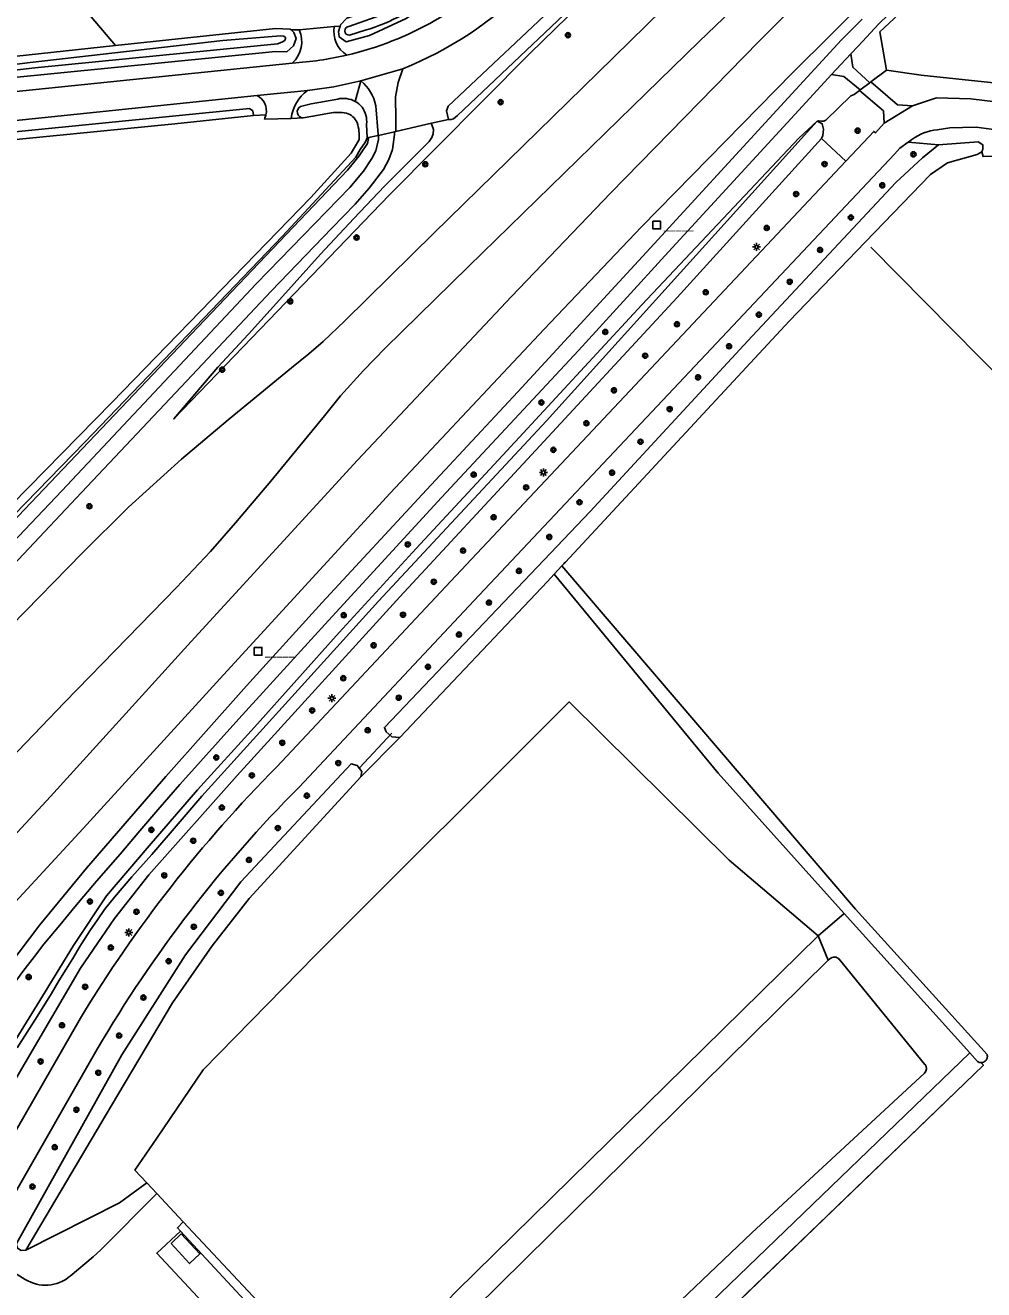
# Model space of a CAD drawing. Extents: x 141000 to 143000, y 400580 to 403500.
# Drawn here: x 141131.1 to 141280.9, y 401460.8 to 401658.2 of the extents above; entities that cross this region are included whole.
import ezdxf

# ---------------------------------------------------------------- set-up
doc = ezdxf.new("R2010")
doc.units = 0
for name, color, linetype in [('gg-afsc-muur', 7, 'Continuous'), ('gg-bbg-luifel en loopbrug', 7, 'Continuous'), ('gg-knt-bronhoudergrens', 7, 'Continuous'), ('gg-knt-onverhard', 7, 'Continuous'), ('gg-knt-verharding', 7, 'Continuous'), ('gg-knt-verharding nz', 7, 'Continuous'), ('gg-kntw-bovenkant insteek waterloop', 7, 'Continuous'), ('gg-kntw-waterlijn', 7, 'Continuous'), ('gg-kwrk-duiker nz buis', 7, 'Continuous'), ('gt-grn-groengrens', 7, 'Continuous'), ('gt-grn-groengrens NZ', 7, 'Continuous'), ('gt-symb-boom', 7, 'Continuous'), ('gt-symb-hm paal', 7, 'Continuous'), ('gt-symb-lichtmast', 7, 'Continuous'), ('gx-grn-maaiveld', 7, 'Continuous')]:
    doc.layers.add(name, color=color, linetype=linetype)

# ---------------------------------------------------------------- blocks, each defined once
blk = doc.blocks.new('gt0-BOOM')
at = {"layer": 'gt-symb-boom'}
for radius in [0.4, 0.2]:
    blk.add_circle((0, 0), radius, dxfattribs=at)
blk = doc.blocks.new('gt0-LMAST')
at = {"layer": 'gt-symb-lichtmast'}
for p, q in [((-0.18, 0.17), (-0.45, 0.44)), ((-0.01, 0.25), (-0.01, 0.62)), ((0.17, 0.17), (0.44, 0.44)), ((-0.26, 0), (-0.63, 0)), ((-0.18, -0.18), (-0.45, -0.45)), ((-0.01, -0.25), (-0.01, -0.63)), ((0.44, -0.45), (0.17, -0.18)), ((0.24, 0), (0.62, 0))]:
    blk.add_line(p, q, dxfattribs=at)
blk.add_circle((-0.01, 0), 0.25, dxfattribs=at)
blk = doc.blocks.new('gt0-HMpaal')
at = {"layer": 'gt-symb-hm paal'}
blk.add_lwpolyline([(-0.6, 0.6), (0.6, 0.6), (0.6, -0.6), (-0.6, -0.6)], close=True, dxfattribs=at)

msp = doc.modelspace()

# ---------------------------------------------------------------- linework, layer by layer
at = {"layer": 'gg-afsc-muur'}
msp.add_line((141190.81, 401409.23), (141280.81, 401495.86), dxfattribs=at)
for points in [[(141307.58, 401634.89), (141295.31, 401636.59), (141285.65, 401637.86), (141280.75, 401637.75)], [(141263.19, 401623.61), (141314.31, 401571.92), (141364.95, 401627.66)], [(141184.12, 401449.64), (141179.93, 401445.63), (141155.78, 401471.4), (141151.62, 401475.84), (141150.06, 401477.51), (141148.21, 401479.48), (141151.64, 401484.46)]]:
    msp.add_lwpolyline(points, dxfattribs=at)
at = {"layer": 'gg-bbg-luifel en loopbrug'}
msp.add_lwpolyline([(141153.86, 401468), (141156.77, 401464.88), (141158.38, 401466.39), (141155.47, 401469.51), (141153.86, 401468)], dxfattribs=at)
at = {"layer": 'gg-knt-bronhoudergrens'}
for p, q in [((141173.89, 401657.55), (141172.61, 401657.51)), ((141180.27, 401658.13), (141179.37, 401658.04)), ((141166.74, 401644.18), (141168.69, 401644.28)), ((141174.53, 401643.79), (141172.64, 401643.69)), ((141256.57, 401512.25), (141256.8, 401512.48)), ((141271.67, 401495.99), (141258.28, 401512.4))]:
    msp.add_line(p, q, dxfattribs=at)
for points in [[(141176.05, 401415.05), (141172.39, 401419), (141180.43, 401426.48), (141176.54, 401431.16), (141193.37, 401447.27), (141193.37, 401449.96), (141256.57, 401512.25)], [(141186.39, 401414.96), (141190.57, 401418.94), (141206.75, 401434.41), (141220.25, 401446.49), (141244.63, 401469.68), (141271.58, 401494.63)]]:
    msp.add_lwpolyline(points, dxfattribs=at)
for centre, start, end in [((141257.51, 401511.76), 39.2641, 134.5353), ((141270.9, 401495.36), 312.8405, 39.1195)]:
    msp.add_arc(centre, 1, start, end, dxfattribs=at)
at = {"layer": 'gg-knt-onverhard'}
msp.add_line((141139.91, 401661.29), (141145.2, 401655.07), dxfattribs=at)
for points in [[(141265.64, 401651.22), (141264.64, 401657.23), (141272, 401664.15), (141296.71, 401681.68), (141298.71, 401679.86), (141305.47, 401686.36)], [(141297.16, 401647.7), (141271.06, 401650.43), (141265.64, 401651.22)], [(141254.96, 401516.05), (141241.05, 401527.9), (141216.1, 401552.59), (141176.39, 401513.02), (141158.87, 401495.13), (141151.64, 401484.46), (141148.21, 401479.48), (141150.06, 401477.51)]]:
    msp.add_lwpolyline(points, dxfattribs=at)
msp.add_arc((141165.99, 401644.88), 2.77, 332.557, 347.6253, dxfattribs=at)
at = {"layer": 'gg-knt-verharding'}
for p, q in [((141173.89, 401657.55), (141179.37, 401658.04)), ((141260.08, 401653.79), (141257.08, 401650.54)), ((141172.81, 401652.33), (141023.85, 401636.99)), ((141263.07, 401649.28), (141261.56, 401648.14)), ((141263.22, 401649.4), (141263.07, 401649.28)), ((141014.52, 401631.57), (141167.3, 401647.27)), ((141261.45, 401648.06), (141261.56, 401648.14)), ((141269.71, 401645.67), (141265.31, 401642.97)), ((141172.64, 401643.69), (141168.45, 401643.6)), ((141186.22, 401641.04), (141186.27, 401641.05)), ((141186.27, 401641.05), (141188.77, 401641.63)), ((141188.77, 401641.63), (141188.99, 401641.68)), ((141139.7, 401503.2), (141117.07, 401463.86)), ((141131.09, 401462.42), (141129.01, 401463.72))]:
    msp.add_line(p, q, dxfattribs=at)
for points in [[(141336.35, 401763.4), (141309.15, 401736.95), (141291.76, 401720.08), (141270.48, 401699.36), (141254.6, 401683.96), (141238.28, 401668.21), (141220.53, 401650.81), (141194.92, 401625.78), (141181, 401612.1), (141177.61, 401608.89), (141175.38, 401606.94), (141172.67, 401604.74), (141162.8, 401596.64), (141155.49, 401590.48), (141147.24, 401582.99), (141139.98, 401575.8), (141128.9, 401564.47), (141117.89, 401552.95), (141106.96, 401541.36), (141097.61, 401531.46), (141096.64, 401530.43)], [(141350.43, 401757.91), (141347.77, 401755.32), (141328.15, 401736.3), (141294.33, 401703.63), (141269.83, 401679.75), (141245.7, 401655.69), (141222.53, 401632.03), (141207.04, 401615.92), (141183.01, 401590.34), (141156.99, 401562), (141135.04, 401537.82), (141112.97, 401514.06)], [(141107.07, 401520.86), (141112.22, 401526.33), (141125.09, 401539.92), (141137.24, 401552.5), (141147.04, 401562.59), (141154.7, 401570.47), (141160.04, 401576.09), (141163.96, 401580.56), (141169.48, 401587.06), (141174.01, 401592.58), (141177.84, 401597.26), (141180.34, 401600.37), (141183.95, 401604.36), (141187.33, 401607.83), (141200.32, 401620.58), (141225.98, 401645.54), (141236.41, 401655.7), (141250.46, 401669.25), (141268.29, 401686.46), (141287.3, 401704.76), (141306.54, 401723.56), (141325.32, 401741.74), (141340.26, 401756.32)], [(141355.42, 401752.82), (141352.36, 401749.86), (141332.87, 401730.87), (141299.6, 401698.77), (141274.97, 401674.65), (141250.99, 401650.8), (141227.4, 401626.76), (141212.15, 401610.78), (141188.12, 401585.2), (141162.06, 401556.84), (141140.14, 401532.81), (141118.27, 401509.2)], [(141359.84, 401748.32), (141342.44, 401731.46), (141323.25, 401712.87), (141309.92, 401699.9), (141306.07, 401696.1), (141302.94, 401693.04), (141299.14, 401689.7), (141295.65, 401686.38), (141291.76, 401682.76), (141288.16, 401679.47), (141285.85, 401677.53), (141282.11, 401674.25), (141277.58, 401670.62), (141274.5, 401667.98), (141271.17, 401664.93), (141267.38, 401661.3), (141264.47, 401658.45), (141261.21, 401655), (141260.08, 401653.79)], [(141261.86, 401659.21), (141258.62, 401655.97), (141247.34, 401643.69), (141229.35, 401624.13), (141208.07, 401601.03), (141193.77, 401585.69), (141177.5, 401568.1), (141165.67, 401555.09), (141153.06, 401540.95), (141140.68, 401526.64), (141133.36, 401517.76), (141126.83, 401509.24), (141123.37, 401504.52)], [(141263.07, 401649.28), (141260.39, 401651.69), (141260.08, 401653.79)], [(141188.99, 401641.68), (141188.97, 401643.59), (141188.94, 401647.08), (141189.33, 401649.33), (141190.07, 401651.46)], [(141125.15, 401502.89), (141128.24, 401507.09), (141130.72, 401510.51), (141132.55, 401512.85), (141134.01, 401514.74), (141136.49, 401517.71), (141138.83, 401520.6), (141142.24, 401524.6), (141145.9, 401528.84), (141149, 401532.46), (141151.78, 401535.72), (141155.26, 401539.69), (141164.44, 401549.93), (141178.46, 401565.3), (141196.11, 401584.49), (141217.53, 401607.44), (141231.57, 401622.89), (141252.51, 401645.6), (141257.08, 401650.54)], [(141183.53, 401649.56), (141179.3, 401648.65), (141176.31, 401648.2), (141175.19, 401648.08)], [(141261.56, 401648.14), (141258.98, 401650.24), (141257.08, 401650.54)], [(141269.71, 401645.67), (141267.4, 401645.82), (141263.22, 401649.4)], [(141265.31, 401642.97), (141265.2, 401644.87), (141261.45, 401648.06)], [(141185.85, 401645.68), (141186.21, 401641.21), (141186.22, 401641.04)], [(141186.27, 401641.05), (141186.26, 401640.39), (141185.84, 401638.62), (141185.25, 401637.46), (141183.94, 401635.47), (141181.81, 401632.93), (141167.22, 401617.93), (141136.82, 401585.57), (141122.31, 401570.35)], [(141188.77, 401641.63), (141188.76, 401641.21), (141188.49, 401638.86), (141187.91, 401637.3), (141187.06, 401635.71), (141184.82, 401632.81), (141182.62, 401630.31), (141178.99, 401626.58), (141169.51, 401616.73), (141156.28, 401602.66), (141139.03, 401584.39), (141124.19, 401568.68)], [(141173.87, 401539.3), (141201.17, 401568.35), (141266.91, 401638.1)], [(141126.99, 401471.44), (141128.92, 401474.97), (141142.33, 401498.36)], [(141151.62, 401475.84), (141142.88, 401467.04), (141141.72, 401465.95), (141138.08, 401462.93)], [(141155.33, 401469.94), (141154.85, 401470.46), (141155.78, 401471.4), (141151.62, 401475.84)], [(141174.34, 401442.18), (141151.64, 401466.51), (141155.33, 401469.94)]]:
    msp.add_lwpolyline(points, dxfattribs=at)
for centre, radius, start, end in [((141169.56, 401703.96), 51.73, 283.1605, 316.0223), ((141168.77, 401704.91), 57.54, 291.7341, 315.0935), ((141169.72, 401655.69), 4.57, 312.5252, 23.9365), ((141183.71, 401657.29), 4.4, 170.1803, 237.4581), ((141179.44, 401644.48), 6.52, 10.5362, 51.1787), ((141166.03, 401644.86), 2.73, 347.8318, 62.223), ((141179, 401642.93), 6.41, 126.4806, 173.1738), ((141320.03, 401393.87), 210.88, 135.2047, 148.7728), ((141319.39, 401394.57), 205.24, 135.155, 149.6224), ((141134.23, 401467.44), 5.92, 237.9134, 310.4501)]:
    msp.add_arc(centre, radius, start, end, dxfattribs=at)
at = {"layer": 'gg-knt-verharding nz'}
for p, q in [((141190.07, 401651.46), (141183.53, 401649.56)), ((141167.3, 401647.27), (141175.19, 401648.08))]:
    msp.add_line(p, q, dxfattribs=at)
msp.add_arc((141169.56, 401704.02), 51.79, 273.5957, 283.1492, dxfattribs=at)
at = {"layer": 'gg-kntw-bovenkant insteek waterloop'}
for p, q in [((141184.51, 401640.65), (141184.43, 401642.82)), ((141259.07, 401519.55), (141278.67, 401497.78)), ((141278.67, 401497.78), (141279.87, 401496.45))]:
    msp.add_line(p, q, dxfattribs=at)
for points in [[(141629.27, 402065.52), (141533.03, 401972.44), (141471.75, 401911.43), (141395.44, 401837.45), (141328.46, 401771.71), (141253.9, 401700.19), (141215.64, 401663.04), (141197.19, 401645.59), (141196.92, 401644.88), (141197.2, 401643.55)], [(141180.27, 401658.13), (141180.03, 401657.28), (141180.16, 401656.43), (141181.21, 401655.66), (141184.88, 401656.63), (141190.59, 401659.32), (141195.13, 401662.54), (141200.98, 401668.07), (141215.64, 401682.1), (141237.39, 401703.32), (141245.57, 401711.56), (141293.05, 401758.14), (141326.46, 401790.25), (141326.77, 401791.32), (141326.34, 401791.82), (141326.29, 401791.84)], [(141197.2, 401643.55), (141197.63, 401643.52), (141198.01, 401643.64), (141198.62, 401644.15), (141223.06, 401667.32), (141261.3, 401704.01), (141302.62, 401744.36), (141334.11, 401774.55)], [(141180.27, 401658.13), (141180.32, 401658.31), (141181.33, 401659.35), (141188.91, 401661.89), (141190.89, 401663.2), (141195.61, 401667.08), (141237.79, 401708.65), (141262.58, 401732.26)], [(141172.61, 401657.51), (141173.04, 401657.14), (141173.42, 401656.17), (141172.98, 401655.05), (141171.97, 401654.12), (141170.18, 401654.13), (141127.72, 401649.95), (141083.47, 401645.11), (141022.31, 401638.67), (141021.93, 401638.95)], [(141172.61, 401657.51), (141172.46, 401657.64), (141170.19, 401657.76), (141145.2, 401655.07)], [(141145.2, 401655.07), (141087.86, 401648.9), (141026.24, 401642.66), (141022.68, 401642.06)], [(141000, 401631.48), (141002.05, 401630.73), (141008.21, 401629.58), (141021.12, 401630.3), (141058.11, 401634.18), (141106.98, 401639.37), (141166.15, 401645.23), (141166.64, 401644.87), (141166.74, 401644.18)], [(141179.91, 401646.72), (141175.77, 401646), (141174.08, 401645.56)], [(141000, 401630.12), (141005.04, 401628.9), (141012.04, 401628.43), (141021.71, 401628.95), (141043.37, 401631.26), (141071.3, 401634.33), (141098.51, 401637.27), (141118.54, 401639.31), (141154.48, 401642.84), (141166.74, 401644.18)], [(141254.84, 401643.29), (141252.33, 401640.51), (141240.29, 401627.17), (141212.52, 401596.46), (141186.29, 401568.34), (141158.7, 401537.85), (141154.65, 401533.21), (141150.87, 401528.75), (141147.76, 401525.3), (141145.05, 401522.09), (141143.49, 401520.2), (141142.39, 401518.59), (141141.17, 401516.85), (141139.62, 401514.4), (141138.53, 401512.53), (141137.5, 401510.86), (141136.34, 401509.05), (141135.18, 401507.06), (141132.93, 401503.45), (141129.83, 401498.59)], [(141174.53, 401643.79), (141176.03, 401644.05), (141178.6, 401644.52)], [(141255.52, 401640.57), (141255.72, 401641.03), (141255.78, 401641.51), (141255.84, 401642), (141255.73, 401642.43), (141255.62, 401642.86), (141255.23, 401643.07), (141254.84, 401643.29)], [(141000, 401586.12), (141018.96, 401565.19), (141061.21, 401518.18), (141062.62, 401517.11), (141063.89, 401516.89), (141064.68, 401516.97), (141076.53, 401529.07), (141105.54, 401559.57), (141144.61, 401599.33), (141175.72, 401631.37), (141182.02, 401638.25), (141183.23, 401640.29)], [(141087.31, 401537.61), (141112.59, 401564.61), (141140.4, 401593.15), (141171.27, 401625.29), (141182.73, 401637.66), (141183.44, 401638.85), (141184.26, 401640.04), (141184.51, 401640.65)], [(141255.52, 401640.57), (141232.95, 401615.74), (141210.2, 401591.15), (141189.64, 401569.02), (141164.21, 401541.12), (141150.42, 401525.59), (141145.02, 401518.79), (141139.7, 401511.02), (141128.74, 401492.22), (141118.77, 401474), (141115.37, 401467.59), (141114.99, 401467.46), (141114.62, 401467.38), (141114.08, 401467.43), (141113.87, 401467.55)], [(141273.78, 401639.56), (141271.3, 401637.55), (141267.1, 401633.71), (141243.98, 401608.99), (141219.35, 401582.34), (141187.21, 401548.62), (141187.49, 401547.93), (141188.38, 401547.12), (141189.6, 401547.02)], [(141280.54, 401638.49), (141280.69, 401638.88), (141280.71, 401639.58), (141279.98, 401640.05), (141273.78, 401639.56)], [(141189.6, 401547.02), (141212.69, 401571.41), (141213.74, 401572.54)], [(141213.74, 401572.54), (141239.36, 401541.44), (141259.07, 401519.55)], [(141131.2, 401466.97), (141130.47, 401466.95), (141129.89, 401467.28), (141129.64, 401467.94), (141146.15, 401497.51), (141156.12, 401513.1), (141164.78, 401524.49), (141182.01, 401542.94), (141182.95, 401542.68), (141183.69, 401541.73), (141183.52, 401540.88)], [(141131.2, 401466.97), (141144.55, 401489.59), (141154.07, 401505.62), (141160.31, 401514.53), (141166.06, 401521.88), (141183.52, 401540.88)]]:
    msp.add_lwpolyline(points, dxfattribs=at)
for centre, radius, start, end in [((141174.54, 401644.73), 0.947, 119.0853, 269.1392), ((141180.79, 401642.98), 3.85, 61.4181, 103.23), ((141180.79, 401642.97), 3.86, 40.4893, 61.3588), ((141180.51, 401643.19), 3.93, 354.6018, 35.425), ((141179.92, 401637.77), 6.88, 78.7571, 101.0708), ((141180.55, 401641.99), 2.62, 24.1141, 74.2699), ((141176.38, 401640.98), 6.89, 354.2593, 17.5515), ((141280.44, 401497.25), 0.987, 234.1461, 269.9399)]:
    msp.add_arc(centre, radius, start, end, dxfattribs=at)
at = {"layer": 'gg-kntw-waterlijn'}
for p, q in [((141187.52, 401660.12), (141181.67, 401658.07)), ((141184.22, 401657.49), (141181.74, 401656.69))]:
    msp.add_line(p, q, dxfattribs=at)
msp.add_lwpolyline([(141023.45, 401640.62), (141023.5, 401640.13), (141023.88, 401640.01), (141039.08, 401641.65), (141064.22, 401644.51), (141091.05, 401647.11), (141114.58, 401649.52), (141132.56, 401651.6), (141170.5, 401655.37), (141171.16, 401655.63), (141171.62, 401655.89), (141171.73, 401656.16), (141171.73, 401656.35), (141171.47, 401656.53), (141170.99, 401656.6), (141161.97, 401655.85), (141131.87, 401652.45), (141107.71, 401649.49), (141076.6, 401646.67), (141047.09, 401643.59), (141024.74, 401641.12), (141023.61, 401640.92), (141023.45, 401640.62)], dxfattribs=at)
for centre, radius, start, end in [((141176.3, 401684.7), 28.35, 286.2061, 311.8296), ((141181.71, 401657.38), 0.69, 92.7424, 272.4099)]:
    msp.add_arc(centre, radius, start, end, dxfattribs=at)
at = {"layer": 'gg-kwrk-duiker nz buis'}
msp.add_line((141188.35, 401547.69), (141183.33, 401542.32), dxfattribs=at)
at = {"layer": 'gt-grn-groengrens'}
for p, q in [((141182.64, 401646.36), (141183.53, 401649.56)), ((141183.52, 401540.88), (141189.6, 401547.02)), ((141259.07, 401519.55), (141254.96, 401516.05)), ((141256.57, 401512.25), (141254.96, 401516.05)), ((141151.62, 401475.84), (141150.06, 401477.51))]:
    msp.add_line(p, q, dxfattribs=at)
for points in [[(141184.7, 401640.7), (141184.72, 401640.55), (141184.54, 401639.81), (141183.69, 401638.5), (141183.27, 401637.85), (141181.43, 401635.62), (141158.03, 401611.11), (141123.93, 401575.3), (141087.57, 401537.37)], [(141254.96, 401516.05), (141198.43, 401460.54), (141181.09, 401442.5), (141178, 401445.6)], [(141278.67, 401497.78), (141206.5, 401428.26), (141196.88, 401417.51), (141190.95, 401412.15), (141188.65, 401414.69), (141187.56, 401413.7)]]:
    msp.add_lwpolyline(points, dxfattribs=at)
at = {"layer": 'gt-grn-groengrens NZ'}
for p, q in [((141197.2, 401643.55), (141194.55, 401642.95)), ((141186.22, 401641.04), (141184.7, 401640.7))]:
    msp.add_line(p, q, dxfattribs=at)
msp.add_lwpolyline([(141131.2, 401466.97), (141145.81, 401474.37), (141150.06, 401477.51)], dxfattribs=at)
at = {"layer": 'gx-grn-maaiveld'}
for p, q in [((141265.64, 401651.22), (141263.22, 401649.4)), ((141188.99, 401641.68), (141194.55, 401642.95)), ((141184.51, 401640.65), (141184.7, 401640.7)), ((141259.3, 401637.02), (141255.52, 401640.57)), ((141269.06, 401640.01), (141269.62, 401640.41)), ((141269.06, 401640.01), (141273.78, 401639.56)), ((141214.93, 401573.82), (141213.74, 401572.54)), ((141155.33, 401469.94), (141178, 401445.6))]:
    msp.add_line(p, q, dxfattribs=at)
for points in [[(141194.55, 401642.95), (141194.58, 401642.87), (141194.85, 401641.96), (141194.83, 401641.3), (141194.61, 401640.73), (141194.21, 401640.09), (141187.2, 401633.11), (141182.43, 401628.07), (141177.2, 401622.52), (141171.28, 401615.92), (141165.99, 401610.01), (141161.2, 401604.88), (141154.32, 401596.77), (141188.01, 401631.77), (141209.91, 401653.84), (141235.43, 401678.72), (141268.37, 401709.73), (141302.22, 401742.79), (141334.53, 401774.13)], [(141254.84, 401643.29), (141255.07, 401643.34), (141255.54, 401643.26), (141255.89, 401643.27), (141256.18, 401643.44), (141260.07, 401647.21), (141260.59, 401647.41), (141261.45, 401648.06)], [(141298.33, 401644.36), (141294.27, 401644.9), (141278.86, 401646.76), (141273.49, 401646.89), (141269.71, 401645.67)], [(141254.84, 401643.29), (141251.94, 401640.62), (141227.45, 401614.59), (141206.36, 401591.79), (141192.16, 401576.55), (141180.14, 401563.42), (141166.91, 401548.65), (141158.01, 401538.84), (141150.43, 401530.13), (141143.8, 401522.29), (141138.62, 401514.58), (141134.21, 401507.3), (141129.18, 401499.19)], [(141259.3, 401637.02), (141262.02, 401639.91), (141263.67, 401641.66), (141263.92, 401641.46), (141265.31, 401642.97)], [(141273.59, 401641.93), (141275.58, 401642.24), (141277.54, 401642.28), (141279.66, 401642.31), (141282.81, 401641.94)], [(141269.06, 401640.01), (141267.73, 401639.06), (141266.91, 401638.1)], [(141170.38, 401542.45), (141197.55, 401571.38), (141259.3, 401637.02)], [(141280.54, 401638.49), (141279.83, 401638.05), (141275.19, 401636.77), (141272.55, 401634.97), (141262.35, 401624.39), (141250.47, 401612.06), (141215.49, 401574.43)], [(141280.54, 401638.49), (141280.75, 401637.75), (141285.65, 401637.86), (141295.31, 401636.59), (141307.58, 401634.89)], [(141215.49, 401574.43), (141215.31, 401574.23), (141215.22, 401574.13), (141215.11, 401574.02), (141214.93, 401573.82)], [(141214.93, 401573.82), (141260.84, 401520.24), (141281.38, 401497.53)], [(141281.38, 401497.53), (141281.4, 401497.45), (141281.41, 401497.37), (141281.42, 401497.29), (141281.42, 401497.2), (141281.41, 401497.12), (141281.4, 401497.04), (141281.38, 401496.96), (141281.35, 401496.88), (141281.32, 401496.8), (141281.27, 401496.73), (141281.23, 401496.66), (141281.18, 401496.6), (141281.12, 401496.54), (141281.06, 401496.48), (141280.99, 401496.43), (141280.92, 401496.39), (141280.85, 401496.35), (141280.77, 401496.32), (141280.69, 401496.3), (141280.61, 401496.28), (141280.52, 401496.27), (141280.44, 401496.26)], [(141188.86, 401407.37), (141190.81, 401409.23), (141280.81, 401495.86), (141280.44, 401496.26)]]:
    msp.add_lwpolyline(points, dxfattribs=at)
msp.add_arc((141274.49, 401633.68), 8.3, 96.2135, 125.8673, dxfattribs=at)

# ---------------------------------------------------------------- block references
at = {"layer": 'gt-symb-boom'}
for p in [(141215.88, 401656.7), (141205.36, 401646.24), (141261.14, 401641.79), (141269.87, 401638.09), (141193.59, 401636.54), (141255.98, 401636.57), (141265, 401633.25), (141251.54, 401631.89), (141260.09, 401628.23), (141182.85, 401625.1), (141246.94, 401626.6), (141255.28, 401623.16), (141250.54, 401618.19), (141172.5, 401615.14), (141237.42, 401616.55), (141245.71, 401613.06), (141232.91, 401611.57), (141221.72, 401610.36), (141241.06, 401608.12), (141227.95, 401606.65), (141161.85, 401604.47), (141236.22, 401603.27), (141223.07, 401601.24), (141211.74, 401599.34), (141231.78, 401598.31), (141218.77, 401596.1), (141227.22, 401593.22), (141213.61, 401591.95), (141201.15, 401588.08), (141222.78, 401588.39), (141209.35, 401586.09), (141217.69, 401583.77), (141141.11, 401583.14), (141204.27, 401581.42), (141212.96, 401578.34), (141190.86, 401577.19), (141199.5, 401576.22), (141208.22, 401573.05), (141194.92, 401571.35), (141203.54, 401568.1), (141180.85, 401566.13), (141190.11, 401566.21), (141198.85, 401563.11), (141185.51, 401561.43), (141194.01, 401558.07), (141180.77, 401556.29), (141189.44, 401553.24), (141175.92, 401551.26), (141184.59, 401548.16), (141171.25, 401546.21), (141160.93, 401543.91), (141179.99, 401543.04), (141166.49, 401541.12), (141175.08, 401537.95), (141161.8, 401536.1), (141150.79, 401532.62), (141170.55, 401532.89), (141157.33, 401530.92), (141166.03, 401527.92), (141152.81, 401525.5), (141161.65, 401522.78), (141141.19, 401521.43), (141148.46, 401519.83), (141157.42, 401517.49), (141144.45, 401514.24), (141153.49, 401512.11), (141131.62, 401509.64), (141140.44, 401508.11), (141149.55, 401506.43), (141136.83, 401502.1), (141145.75, 401500.49), (141133.48, 401496.45), (141142.49, 401494.69), (141139.07, 401488.91), (141135.69, 401483.06), (141132.21, 401476.91)]:
    msp.add_blockref('gt0-BOOM', p, dxfattribs=at)
at = {"layer": 'gt-symb-hm paal'}
for p in [(141229.77, 401627.04), (141167.47, 401560.49)]:
    msp.add_blockref('gt0-HMpaal', p, dxfattribs=at)
at = {"layer": 'gt-symb-lichtmast'}
for p in [(141245.36, 401623.63), (141212.06, 401588.42), (141179.02, 401553.17), (141147.28, 401516.59)]:
    msp.add_blockref('gt0-LMAST', p, dxfattribs=at)

# ---------------------------------------------------------------- texts
at = {"layer": 'gt-symb-hm paal'}
for p in [(141230.85, 401626.44), (141168.55, 401559.88)]:
    msp.add_text('_____', height=1.25, dxfattribs=at).set_placement(p)

doc.saveas('drawing.dxf')
